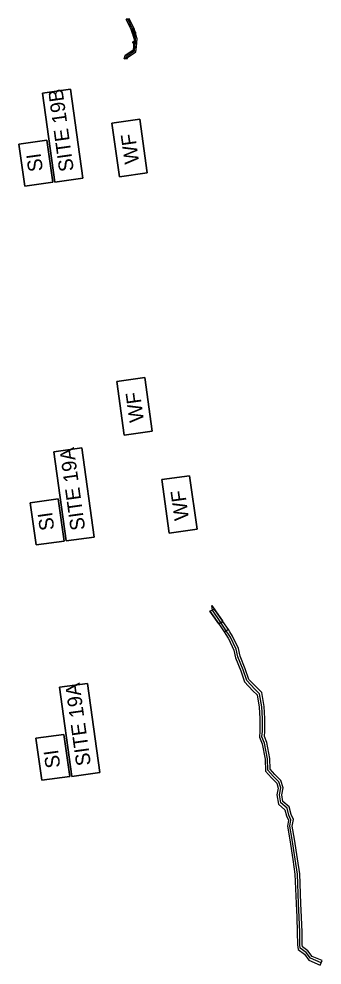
# Model space of a CAD drawing. Extents: x 474218 to 481634, y 484357 to 504997.
# Drawn here: x 477741 to 478054, y 497664 to 498639 of the extents above; entities that cross this region are included whole.
import ezdxf

# ---------------------------------------------------------------- set-up
doc = ezdxf.new("R2010")
doc.units = 0
for name, color, linetype in [('Exist Hydro Jurisdictional Stream or Body of Water', 7, 'Continuous'), ('Old_Level_29', 7, 'Continuous'), ('Old_Level_30', 7, 'Continuous'), ('Prop Earthen Structure Impacts In Surface Waters Hatching CELL', 7, 'Continuous'), ('Prop Grid Mask', 7, 'Continuous'), ('Scratch_Level_4', 7, 'Continuous'), ('Temp Earthen Structure Impacts In Surface Waters Hatching CELL', 7, 'Continuous')]:
    doc.layers.add(name, color=color, linetype=linetype)

msp = doc.modelspace()

# ---------------------------------------------------------------- linework, layer by layer
at = {"layer": 'Exist Hydro Jurisdictional Stream or Body of Water'}
for points in [[(477747.34, 498466.76), (477741.32, 498510.07), (477770.12, 498514.08), (477776.15, 498470.77)], [(477759.1, 498097.08), (477753.07, 498140.39), (477781.88, 498144.4), (477787.91, 498101.09)], [(477764.94, 497854.59), (477758.91, 497897.9), (477787.72, 497901.91), (477793.75, 497858.59)]]:
    msp.add_lwpolyline(points, close=True, dxfattribs=at)
at = {"layer": 'Old_Level_29'}
for points in [[(477778.4, 498470.85), (477765.63, 498562.62), (477794.44, 498566.63), (477807.21, 498474.86)], [(477790.16, 498101.17), (477777.38, 498192.94), (477806.2, 498196.95), (477818.97, 498105.18)], [(477796, 497858.68), (477783.22, 497950.45), (477812.04, 497954.46), (477824.81, 497862.69)]]:
    msp.add_lwpolyline(points, close=True, dxfattribs=at)
at = {"layer": 'Old_Level_30'}
for points in [[(477844.8, 498476.37), (477837.11, 498531.62), (477865.92, 498535.63), (477873.61, 498480.38)], [(477849.79, 498210.22), (477842.1, 498265.47), (477870.91, 498269.48), (477878.6, 498214.23)], [(477896.09, 498109.16), (477888.4, 498164.41), (477917.21, 498168.42), (477924.9, 498113.17)]]:
    msp.add_lwpolyline(points, close=True, dxfattribs=at)
at = {"layer": 'Prop Earthen Structure Impacts In Surface Waters Hatching CELL'}
for p, q in [((477859.35, 498610.79), (477862.31, 498610.17)), ((477862.31, 498610.17), (477863, 498618.42)), ((477952.7, 498007.51), (477957.08, 498009.94)), ((478053.66, 497668.84), (478043.39, 497673.24)), ((478051.69, 497664.24), (478053.66, 497668.84))]:
    msp.add_line(p, q, dxfattribs=at)
for points in [[(477863, 498618.42), (477859.95, 498628.83), (477857.11, 498627.86), (477859.96, 498618.11), (477859.35, 498610.79)], [(477957.08, 498009.94), (477951.57, 498018.3), (477947.26, 498015.73), (477952.69, 498007.51), (477952.7, 498007.51)], [(477958.67, 498007.51), (477957.08, 498009.94), (477957.08, 498009.94), (477952.69, 498007.51), (477952.69, 498007.51), (477957, 498000.91)], [(478043.39, 497673.24), (478039.07, 497679.08), (478033.56, 497683.19), (478033.27, 497685.32), (478033.13, 497698.13), (478032.57, 497713.76), (478031.88, 497727.73), (478030.71, 497758.21), (478028.49, 497773.7), (478025.26, 497794.01), (478023, 497807.43), (478024.11, 497814.17), (478021.81, 497819.46), (478019.8, 497827.09), (478013.33, 497832.76), (478012.18, 497839.62), (478013.6, 497846.86), (478011.29, 497854.37), (478005.11, 497860.42), (478000.32, 497865.94), (477999.96, 497877.03), (477996.85, 497893.67), (477994.29, 497899.75), (477994.67, 497905.08), (477994.7, 497918.26), (477993.93, 497930.56), (477991.44, 497944.94), (477986.04, 497950.37), (477978.21, 497958.57), (477974.57, 497969.27), (477969.11, 497982.35), (477967.55, 497990.3), (477961.5, 498003.16), (477958.67, 498007.51)], [(477957, 498000.91), (477957.13, 498000.72), (477962.76, 497988.73), (477964.3, 497980.89), (477969.89, 497967.5), (477973.84, 497955.92), (477982.46, 497946.88), (477986.78, 497942.53), (477988.95, 497929.97), (477989.7, 497918.11), (477989.67, 497905.27), (477989.22, 497898.91), (477992.03, 497892.22), (477994.97, 497876.48), (477995.39, 497864), (478001.46, 497856.99), (478006.88, 497851.69), (478008.45, 497846.59), (478007.1, 497839.69), (478008.69, 497830.17), (478015.35, 497824.34), (478017.07, 497817.82), (478018.93, 497813.53), (478017.93, 497807.42), (478020.33, 497793.2), (478023.54, 497772.95), (478025.72, 497757.76), (478026.88, 497727.51), (478027.57, 497713.55), (478028.13, 497698.01), (478028.28, 497684.96), (478028.88, 497680.45), (478035.49, 497675.51), (478040.18, 497669.18), (478051.69, 497664.24)]]:
    msp.add_lwpolyline(points, dxfattribs=at)
for points in [[(477858.33, 498623.59), (477858.35, 498623.54), (477858.23, 498624.41), (477858.22, 498624.39), (477858.22, 498623.96), (477858.22, 498623.96)], [(477859.42, 498623.07), (477859.55, 498623.1), (477859.45, 498623.76), (477859.34, 498623.67), (477859.14, 498623.63), (477859.13, 498623.62), (477859.08, 498623.64), (477858.95, 498623.67), (477858.9, 498623.71), (477858.83, 498623.77), (477858.8, 498623.8), (477858.79, 498623.83), (477858.76, 498623.91), (477858.71, 498624.02), (477858.58, 498624.98), (477858.52, 498624.95), (477858.37, 498624.77), (477858.33, 498624.73), (477858.23, 498624.41), (477858.35, 498623.54), (477858.53, 498623.31), (477858.58, 498623.25), (477858.77, 498623.14), (477858.84, 498623.1), (477858.87, 498623.09), (477858.9, 498623.07), (477858.9, 498623.07), (477858.93, 498623.07), (477858.99, 498623.06), (477859.04, 498623.06), (477859.17, 498623.04), (477859.21, 498623.03), (477859.23, 498623.03)], [(477858.83, 498624.51), (477858.95, 498624.63), (477858.79, 498624.85), (477858.73, 498624.93), (477858.66, 498625.04), (477858.63, 498625.02), (477858.63, 498625.02), (477858.6, 498625), (477858.58, 498624.98), (477858.71, 498624.02), (477858.71, 498624.27), (477858.72, 498624.31), (477858.73, 498624.32), (477858.75, 498624.37), (477858.8, 498624.47)], [(477859.74, 498623.23), (477859.81, 498623.28), (477859.68, 498624.21), (477859.63, 498624.03), (477859.51, 498623.8), (477859.45, 498623.76), (477859.55, 498623.1), (477859.6, 498623.14)], [(477861.28, 498624.58), (477861.35, 498624.37), (477861.22, 498625.34), (477861.18, 498625.36), (477861.17, 498625.36), (477861.16, 498625.37), (477861.09, 498625.4), (477861.06, 498625.41), (477861.04, 498625.41), (477860.93, 498625.42), (477860.89, 498625.42), (477860.85, 498625.42), (477860.71, 498625.43), (477860.63, 498625.41), (477860.44, 498625.36), (477860.36, 498625.34), (477860.29, 498625.29), (477860.17, 498625.2), (477860.17, 498625.2), (477860.07, 498625.12), (477860.02, 498625.03), (477859.88, 498624.79), (477859.85, 498624.71), (477859.73, 498624.38), (477859.68, 498624.21), (477859.81, 498623.27), (477859.88, 498623.36), (477860.01, 498623.54), (477860.04, 498623.61), (477860.17, 498623.92), (477860.22, 498624.07), (477860.3, 498624.3), (477860.39, 498624.57), (477860.45, 498624.65), (477860.53, 498624.75), (477860.71, 498624.84), (477860.8, 498624.84), (477860.93, 498624.84), (477860.97, 498624.83), (477861.02, 498624.81), (477861.13, 498624.78), (477861.15, 498624.75), (477861.18, 498624.71), (477861.27, 498624.61), (477861.28, 498624.6)], [(477861.86, 498623.93), (477861.87, 498624.42), (477861.73, 498624.9), (477861.73, 498624.9), (477861.47, 498625.21), (477861.43, 498625.24), (477861.22, 498625.34), (477861.35, 498624.37), (477861.35, 498624.1), (477861.35, 498624.1), (477861.34, 498624.08), (477861.29, 498623.94), (477861.27, 498623.88), (477861.25, 498623.86), (477861.16, 498623.76), (477861.12, 498623.72), (477861.09, 498623.7), (477860.97, 498623.63), (477861.14, 498623.37), (477861.18, 498623.3), (477861.24, 498623.21), (477861.34, 498623.26), (477861.36, 498623.27), (477861.38, 498623.28), (477861.45, 498623.31), (477861.46, 498623.32), (477861.46, 498623.32), (477861.49, 498623.36), (477861.67, 498623.52), (477861.7, 498623.55), (477861.86, 498623.92)], [(477859.83, 498613.69), (477859.95, 498613.72), (477859.86, 498614.38), (477859.74, 498614.28), (477859.55, 498614.24), (477859.54, 498614.24), (477859.49, 498614.25), (477859.36, 498614.29), (477859.31, 498614.33), (477859.24, 498614.39), (477859.21, 498614.42), (477859.2, 498614.44), (477859.16, 498614.53), (477859.12, 498614.64), (477858.99, 498615.6), (477858.93, 498615.57), (477858.78, 498615.39), (477858.74, 498615.34), (477858.63, 498615.03), (477858.75, 498614.16), (477858.94, 498613.93), (477858.99, 498613.86), (477859.18, 498613.76), (477859.25, 498613.72), (477859.28, 498613.7), (477859.3, 498613.69), (477859.31, 498613.69), (477859.34, 498613.69), (477859.4, 498613.68), (477859.44, 498613.67), (477859.57, 498613.66), (477859.62, 498613.65), (477859.64, 498613.65)], [(477858.74, 498614.2), (477858.75, 498614.16), (477858.63, 498615.03), (477858.63, 498615.01), (477858.63, 498614.57), (477858.63, 498614.57)], [(477859.24, 498615.13), (477859.35, 498615.25), (477859.19, 498615.47), (477859.14, 498615.55), (477859.07, 498615.65), (477859.04, 498615.64), (477859.03, 498615.63), (477859.01, 498615.62), (477858.99, 498615.6), (477859.12, 498614.64), (477859.11, 498614.89), (477859.13, 498614.92), (477859.14, 498614.94), (477859.16, 498614.98), (477859.2, 498615.09)], [(477860.15, 498613.85), (477860.22, 498613.89), (477860.09, 498614.82), (477860.04, 498614.65), (477859.92, 498614.42), (477859.86, 498614.38), (477859.95, 498613.72), (477860.01, 498613.75)], [(477861.69, 498615.2), (477861.76, 498614.99), (477861.62, 498615.96), (477861.58, 498615.98), (477861.58, 498615.98), (477861.57, 498615.99), (477861.5, 498616.02), (477861.47, 498616.02), (477861.45, 498616.03), (477861.34, 498616.03), (477861.3, 498616.04), (477861.26, 498616.04), (477861.12, 498616.05), (477861.04, 498616.03), (477860.85, 498615.98), (477860.76, 498615.96), (477860.7, 498615.91), (477860.58, 498615.82), (477860.58, 498615.82), (477860.48, 498615.74), (477860.43, 498615.65), (477860.29, 498615.41), (477860.26, 498615.33), (477860.14, 498615), (477860.09, 498614.82), (477860.22, 498613.89), (477860.28, 498613.98), (477860.42, 498614.16), (477860.45, 498614.23), (477860.58, 498614.54), (477860.63, 498614.69), (477860.7, 498614.92), (477860.8, 498615.19), (477860.86, 498615.27), (477860.93, 498615.36), (477861.12, 498615.46), (477861.2, 498615.46), (477861.34, 498615.46), (477861.38, 498615.45), (477861.42, 498615.43), (477861.53, 498615.39), (477861.56, 498615.36), (477861.59, 498615.33), (477861.68, 498615.23), (477861.69, 498615.22)], [(477862.27, 498614.55), (477862.28, 498615.04), (477862.14, 498615.52), (477862.14, 498615.52), (477861.87, 498615.82), (477861.84, 498615.86), (477861.62, 498615.96), (477861.76, 498614.99), (477861.76, 498614.72), (477861.76, 498614.72), (477861.75, 498614.7), (477861.7, 498614.55), (477861.68, 498614.5), (477861.66, 498614.48), (477861.57, 498614.38), (477861.53, 498614.34), (477861.5, 498614.32), (477861.38, 498614.25), (477861.54, 498613.99), (477861.59, 498613.92), (477861.65, 498613.83), (477861.74, 498613.88), (477861.77, 498613.89), (477861.79, 498613.9), (477861.86, 498613.93), (477861.87, 498613.94), (477861.87, 498613.94), (477861.9, 498613.97), (477862.08, 498614.14), (477862.1, 498614.16), (477862.27, 498614.54)]]:
    msp.add_lwpolyline(points, close=True, dxfattribs=at)
at = {"layer": 'Prop Grid Mask'}
for points in [[(477807.21, 498474.86), (477794.44, 498566.63), (477765.63, 498562.62), (477778.4, 498470.85)], [(477873.61, 498480.38), (477865.92, 498535.63), (477837.11, 498531.62), (477844.8, 498476.37)], [(477776.15, 498470.77), (477770.12, 498514.08), (477741.32, 498510.07), (477747.34, 498466.76)], [(477878.6, 498214.23), (477870.91, 498269.48), (477842.1, 498265.47), (477849.79, 498210.22)], [(477818.97, 498105.18), (477806.2, 498196.95), (477777.38, 498192.94), (477790.16, 498101.17)], [(477924.9, 498113.17), (477917.21, 498168.42), (477888.4, 498164.41), (477896.09, 498109.16)], [(477787.91, 498101.09), (477781.88, 498144.4), (477753.07, 498140.39), (477759.1, 498097.08)], [(477824.81, 497862.69), (477812.04, 497954.46), (477783.22, 497950.45), (477796, 497858.68)], [(477793.75, 497858.59), (477787.72, 497901.91), (477758.91, 497897.9), (477764.94, 497854.59)]]:
    msp.add_lwpolyline(points, close=True, dxfattribs=at)
at = {"layer": 'Scratch_Level_4'}
for p, q in [((477851.91, 498638.53), (477854.88, 498638.95)), ((477853.02, 498598.3), (477849.77, 498597.85)), ((477949.41, 498017.11), (477940.71, 498029.96)), ((477954.91, 498008.68), (477949.41, 498017.11))]:
    msp.add_line(p, q, dxfattribs=at)
for points in [[(477850.7, 498601.18), (477849.77, 498597.85), (477853.02, 498598.3), (477853.3, 498599.31), (477861.9, 498605.13), (477863, 498618.42), (477860.91, 498625.56), (477859.81, 498629.31), (477854.89, 498638.9), (477851.91, 498638.53), (477852.02, 498637.94), (477855.59, 498630.71), (477857.03, 498628.14), (477857.62, 498626.11), (477859.96, 498618.11), (477859.02, 498606.78), (477857.62, 498605.83)], [(477858.55, 498622.93), (477857.03, 498628.14), (477855.59, 498630.71), (477852.02, 498637.94), (477851.91, 498638.53), (477854.89, 498638.9), (477859.81, 498629.31), (477861.51, 498623.51)], [(477947.26, 498015.73), (477939.57, 498026.48), (477938.05, 498028.78), (477940.71, 498029.96), (477940.09, 498034.75), (477943.69, 498029.32), (477951.2, 498018.81), (477951.57, 498018.3)], [(477952.69, 498007.5), (477957.13, 498009.98), (477951.57, 498018.3), (477947.26, 498015.73)]]:
    msp.add_lwpolyline(points, close=True, dxfattribs=at)
for points in [[(477858.57, 498628.36), (477858.45, 498628.76), (477853.48, 498638.93)], [(477860.85, 498610.47), (477861.45, 498618.68), (477858.57, 498628.36)], [(477851.47, 498598.21), (477852.57, 498600.71), (477860.41, 498605.94), (477860.85, 498610.47)], [(477849.77, 498597.85), (477850.7, 498601.18), (477859.02, 498606.78)], [(477957.83, 498004.21), (477954.91, 498008.68)], [(478052.68, 497666.54), (478041.78, 497671.21), (478037.28, 497677.3), (478031.22, 497681.82), (478030.77, 497685.14), (478030.63, 497698.07), (478030.07, 497713.65), (478029.38, 497727.62), (478028.22, 497757.99), (478026.02, 497773.32), (478022.8, 497793.6), (478020.47, 497807.43), (478021.52, 497813.85), (478019.44, 497818.64), (478017.57, 497825.72), (478011.01, 497831.47), (478009.64, 497839.66), (478011.02, 497846.72), (478009.08, 497853.03), (478003.29, 497858.71), (477997.86, 497864.97), (477997.47, 497876.76), (477994.44, 497892.95), (477991.76, 497899.33), (477992.17, 497905.18), (477992.2, 497918.18), (477991.44, 497930.26), (477989.11, 497943.73), (477984.25, 497948.62), (477976.03, 497957.25), (477972.23, 497968.38), (477966.71, 497981.62), (477965.15, 497989.52), (477959.32, 498001.94), (477957.83, 498004.21)]]:
    msp.add_lwpolyline(points, dxfattribs=at)
at = {"layer": 'Temp Earthen Structure Impacts In Surface Waters Hatching CELL'}
msp.add_line((477862.31, 498610.17), (477859.35, 498610.79), dxfattribs=at)
for points in [[(477859.95, 498628.83), (477859.81, 498629.31), (477858.24, 498632.11), (477854.89, 498638.9), (477851.91, 498638.53), (477852.02, 498637.94), (477855.59, 498630.71), (477857.03, 498628.14), (477857.11, 498627.86), (477859.95, 498628.83)], [(477859.35, 498610.79), (477859.02, 498606.78), (477850.7, 498601.18), (477849.77, 498597.85), (477853.02, 498598.3), (477853.3, 498599.31), (477861.9, 498605.13), (477862.31, 498610.17)], [(477951.57, 498018.3), (477951.2, 498018.81), (477943.69, 498029.32), (477942.64, 498030.9), (477940.71, 498029.96), (477938.05, 498028.78), (477939.57, 498026.48), (477947.26, 498015.73), (477951.57, 498018.3)]]:
    msp.add_lwpolyline(points, dxfattribs=at)

# ---------------------------------------------------------------- texts
at = {"layer": 'Exist Hydro Jurisdictional Stream or Body of Water'}
for p in [(477766.16, 498482.61), (477777.92, 498112.93), (477784.08, 497868.14)]:
    msp.add_text('SI', height=15, rotation=97.92303, dxfattribs=at).set_placement(p)
at = {"layer": 'Old_Level_29'}
for s, p in [('SITE 19B', (477797.95, 498482.7)), ('SITE 19A', (477809.71, 498113.02)), ('SITE 19A', (477815.55, 497870.52))]:
    msp.add_text(s, height=15, rotation=97.92303, dxfattribs=at).set_placement(p)
at = {"layer": 'Old_Level_30'}
for p in [(477865.28, 498490.68), (477870.27, 498224.53), (477916.57, 498123.47)]:
    msp.add_text('WF', height=15, rotation=97.92303, dxfattribs=at).set_placement(p)

doc.saveas('drawing.dxf')
